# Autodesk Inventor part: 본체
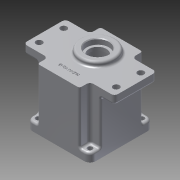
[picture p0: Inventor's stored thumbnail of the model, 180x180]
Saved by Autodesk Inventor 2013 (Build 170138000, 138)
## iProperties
Created: 2015-07
Part Number: 본체
Material: 알루미늄 6061
Document SubType Name: 판금
Designer: user
Density: 1 g/cm^3
Sheet Metal Rule: 기본값
Author: user
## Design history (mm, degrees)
node "작업 평면1"
sketch "스케치2"
  geometry: L1 (-30, 45)-(30, 45); L2 (30, -45)-(-30, -45); L3 (65, 30)-(65, -30); L4 (-65, -30)-(-65, 30); L5 (-30, -45)-(-30, -35); L6 (-30, 35)-(-30, 45); L7 (-65, 30)-(-35, 30); L8 (35, 30)-(65, 30); L9 (30, 45)-(30, 35); L10 (30, -35)-(30, -45); L11 (65, -30)-(35, -30); L12 (-35, -30)-(-65, -30); A1 r 5 centre (-35, 35) between (-35, 30) and (-30, 35); A2 r 5 centre (35, 35) between (30, 35) and (35, 30); A3 r 5 centre (35, -35) between (35, -30) and (30, -35); A4 r 5 centre (-35, -35) between (-30, -35) and (-35, -30); 4 further points
  constraints: 24 end point, 10 parallel, 8 point on circle, 8 tangent, 4 centre point, 4 perpendicular, 3 equal radius, 3 horizontal, 2 horizontal alignment, 2 midpoint, 1 vertical alignment
  dimensions: "d5" = 60 distance of L2.start L2.end; "d6" = 90 distance of L1.end L2.start; "d9" = 130 distance of L3.end L4.start; "d10" = 60 distance of L3.start L3.end; "d11" = 65 distance from line of L4 point (0, 0); "d12" = 5 radius of A1
extrude "돌출2" join sketch "스케치2" distance "d13" = 12; taper "d14" = 0 deg
sketch "스케치4"
  geometry: L1 (-30, 45)-(30, 45); L2 (30, 45)-(30, -45); L3 (30, -45)-(-30, -45); L4 (-30, -45)-(-30, 45); 1 further point
  constraints: 8 end point, 2 parallel, 1 horizontal, 1 perpendicular
extrude "돌출3" join sketch "스케치4" distance "d19" = 63; taper "d20" = 0 deg
sketch "스케치5"
  geometry: L1 (35, 30)-(65, 30) reference; L2 (65, 30)-(65, -30) reference; L3 (65, -30)-(35, -30) reference; L4 (30, 35)-(30, -35) reference; L5 (30, 45)-(30, 35) reference; L6 (-30, 45)-(30, 45) reference; L7 (-30, 35)-(-30, 45) reference; L8 (-65, 30)-(-35, 30) reference; L9 (-65, -30)-(-65, 30) reference; L10 (-35, -30)-(-65, -30) reference; L11 (-30, -35)-(-30, 35) reference; L12 (30, -35)-(30, -45) reference; L13 (30, -45)-(-30, -45) reference; L14 (-30, -45)-(-30, -35) reference; L15 (30, 30)-(46, 30); L16 (46, 30)-(46, -30); L17 (46, -30)-(30, -30); L18 (30, -30)-(30, 30); L19 (-46, 30)-(-46, -30); L20 (-30, -30)-(-30, 30); L21 (-30, 30)-(-46, 30); L22 (-46, -30)-(-30, -30); A1 r 5 centre (35, 35) between (30, 35) and (35, 30) reference; A2 r 5 centre (35, -35) between (35, -30) and (30, -35) reference; A3 r 5 centre (-35, 35) between (-35, 30) and (-30, 35) reference; A4 r 5 centre (-35, -35) between (-30, -35) and (-35, -30) reference; 1 further point
  constraints: 16 end point, 3 parallel, 1 horizontal, 1 perpendicular, 1 point on line
  dimensions: "d21" = 16 distance of L16.end L17.end; "d22" = 60 distance of L15.end L16.end; "d23" = 90 deg angle of L2 L21; "d24" = 90 deg angle of L2 L22; "d25" = 90 deg angle of L3 L20; "d26" = 111 distance between parallel lines of L2 L19; "d27" = 60 distance between parallel lines of L3 L15; "d28" = 95 distance from line of L1.end L20; "d29" = 0 distance from line of L1.end L21; "d30" = 60 distance from line of L1.end L22
extrude "돌출4" join sketch "스케치5" distance "d31" = 63; taper "d32" = 0 deg
fillet "모깎기1" dims "d33" = 5
sketch "스케치6"
  geometry: L1 (-45, 45)-(45, 45); L2 (45, 45)-(45, -45); L3 (45, -45)-(-45, -45); L4 (-45, -45)-(-45, 45); 3 further points
  constraints: 8 end point, 2 midpoint, 2 parallel, 1 horizontal, 1 horizontal alignment, 1 perpendicular, 1 vertical alignment
  dimensions: "d34" = 90 distance of L2.end L3.end; "d35" = 90 distance of L1.end L2.end
extrude "돌출5" join sketch "스케치6" distance "d36" = 12; taper "d37" = 0 deg
sketch "스케치7"
  geometry: L1 (45, 45)-(-45, 45) reference; L2 (-45, 45)-(-45, -45) reference; L3 (-45, -45)-(45, -45) reference; L4 (45, -45)-(45, 45) reference; 1 further point
sketch "스케치8"
  geometry: L1 (45, 45)-(-45, 45) reference; L2 (-45, 45)-(-45, -45) reference; L3 (-45, -45)-(45, -45) reference; L4 (45, -45)-(45, 45) reference; 1 further point
sketch "스케치9"
  geometry: L1 (45, 45)-(-45, 45) reference; L2 (-45, 45)-(-45, -45) reference; L3 (-45, -45)-(45, -45) reference; L4 (45, -45)-(45, 45) reference; 1 further point
sketch "스케치10"
  geometry: L1 (-37, 37)-(37, 37); L2 (37, 37)-(37, -37); L3 (37, -37)-(-37, -37); L4 (-37, -37)-(-37, 37); C1 r 3.5 at (-37, 37); C2 r 3.5 at (37, 37); C3 r 3.5 at (-37, -37); C4 r 3.5 at (37, -37); 3 further points
  constraints: 8 end point, 4 centre point, 4 coincident, 2 midpoint, 2 parallel, 1 horizontal, 1 horizontal alignment, 1 perpendicular, 1 vertical alignment
  dimensions: "d38" = 74 distance of L2.end L3.end; "d39" = 74 distance of L1.end L2.end; "d40" = 7 diameter of C1; "d41" = 7 diameter of C2; "d42" = 7 diameter of C3; "d43" = 7 diameter of C4
extrude "돌출6" cut sketch "스케치10" distance "d44" = 12; taper "d45" = 0 deg
fillet "모깎기2" dims "d46" = 8
sketch "스케치11"
  geometry: L1 (-55, 17.5)-(55, 17.5); L2 (55, 17.5)-(55, -17.5); L3 (55, -17.5)-(-55, -17.5); L4 (-55, -17.5)-(-55, 17.5); 7 further points
  constraints: 8 end point, 4 coincident, 2 midpoint, 2 parallel, 1 horizontal, 1 horizontal alignment, 1 perpendicular, 1 vertical alignment
  dimensions: "d47" = 110 distance of L2.end L3.end; "d48" = 35 distance of L1.end L2.end
hole "구멍1" sketch "스케치11" at (-55, 17.5), (55, 17.5), (55, -17.5), (-55, -17.5) diameter "d49" = 9; stored, may be unused: countersink angle "d53" = 90 deg, drill point angle "d55" = 118 deg; dims "d50" = 6, "d51" = 4, "d52" = 2, "d54" = 0.5 (derived)
fillet "모깎기3" dims "d56" = 5
sketch "스케치12"
  geometry: L1 (67, 75)-(67, 87) reference; L2 (-7, 87)-(67, 87) reference; L3 (-7, 75)-(-7, 87) reference; L4 (0, 75)-(-7, 75) reference; L5 (0, 0)-(0, 75) reference; L6 (60, 0)-(0, 0) reference; L7 (60, 75)-(60, 0) reference; L8 (67, 75)-(60, 75) reference; L9 (-16, 12)-(-16, 75) reference; L10 (-15, 87)-(-15, 75) reference; L11 (76, 12)-(76, 75) reference; L12 (75, 75)-(67, 75) reference; L13 (75, 75)-(75, 87) reference; L14 (75, 75)-(76, 75); L15 (76, 75)-(76, 12); L16 (76, 12)-(75, 12); L17 (75, 12)-(75, 75); L18 (-15, 75)-(-16, 75); L19 (-16, 75)-(-16, 12); L20 (-16, 12)-(-15, 12); L21 (-15, 12)-(-15, 75); 1 further point
  constraints: 16 end point, 4 parallel, 2 horizontal, 2 perpendicular
extrude "돌출7" cut sketch "스케치12" distance "d57" = 63; taper "d58" = 0 deg
sketch "스케치13"
  geometry: 1 further point
hole "구멍2" sketch "스케치13" at (0, 0) diameter "d59" = 80; stored, may be unused: countersink angle "d63" = 90 deg, drill point angle "d65" = 0 deg; dims "d60" = 6, "d61" = 4, "d62" = 2, "d64" = 9
sketch "스케치15"
  geometry: C1 r 40 at (0, 0) reference; C2 r 39 at (0, 0)
  constraints: 1 centre point, 1 coincident
  dimensions: "d77" = 78 diameter of C2
extrude "돌출8" cut sketch "스케치15" distance "d78" = 52; taper "d79" = 0 deg
node "작업 평면2"
sketch "스케치16" dims "d81" = 70
  geometry: L1 (0, 0)-(60.287, 60.287); L2 (0, 0)-(85.258, 0); A1 r 4 centre (24.749, 24.749) between (23.219, 28.445) and (28.445, 23.219); A2 r 40 centre (0, 0) between (25.309, 30.975) and (30.975, 25.309) reference; A3 r 3.5 centre (31.678, 21.88) between (30.975, 25.309) and (28.445, 23.219); A4 r 3.5 centre (21.88, 31.678) between (23.219, 28.445) and (25.309, 30.975); A5 r 3.5 centre (-31.678, 21.88) between (-28.445, 23.219) and (-30.975, 25.309); A6 r 4 centre (-24.749, 24.749) between (-28.445, 23.219) and (-23.219, 28.445); A7 r 3.5 centre (-21.88, 31.678) between (-25.309, 30.975) and (-23.219, 28.445); A8 r 3.5 centre (-21.88, -31.678) between (-23.219, -28.445) and (-25.309, -30.975); A9 r 4 centre (-24.749, -24.749) between (-23.219, -28.445) and (-28.445, -23.219); A10 r 3.5 centre (-31.678, -21.88) between (-30.975, -25.309) and (-28.445, -23.219); A11 r 3.5 centre (31.678, -21.88) between (28.445, -23.219) and (30.975, -25.309); A12 r 4 centre (24.749, -24.749) between (28.445, -23.219) and (23.219, -28.445); A13 r 3.5 centre (21.88, -31.678) between (25.309, -30.975) and (23.219, -28.445); 1 further point
  constraints: 26 point on circle, 12 centre point, 4 end point, 1 coincident, 1 equal length, 1 horizontal, 1 point on line, 1 symmetric about line, 1 tangent, 46 other
  dimensions: "d82" = 45 deg angle of L2 L1; "d83" = 8 diameter of A1; "d84" = 7 diameter of A3; "d87" = 360 deg dimension on point (0, 0) A4.centre (derived)
extrude "돌출9" join sketch "스케치16" distance "d89" = 54; taper "d90" = 0 deg
fillet "모깎기4" dims "d94" = 3.5
sketch "스케치17"
  geometry: L1 (-65, -25)-(-65, 25) reference; L2 (0, 0)-(0, 11); C1 r 25 at (0, 11)
  constraints: 2 end point, 1 centre point, 1 coincident, 1 parallel
  dimensions: "d95" = 11 distance of L2.start L2.end; "d96" = 50 diameter of C1
extrude "돌출10" join sketch "스케치17" distance "d97" = 7; taper "d98" = 0 deg
sketch "스케치18"
  geometry: C1 r 25 at (0, 0) reference; 1 further point
hole "구멍3" sketch "스케치18" at (0, 0) diameter "d99" = 25; stored, may be unused: countersink angle "d103" = 90 deg, drill point angle "d105" = 0 deg; dims "d100" = 6, "d101" = 32, "d102" = 8, "d104" = 13
sketch "스케치19"
  geometry: C1 r 12.5 at (0, 0) reference; 1 further point
hole "구멍4" sketch "스케치19" at (0, 0) diameter "d106" = 35; stored, may be unused: countersink angle "d110" = 90 deg, drill point angle "d112" = 0 deg; dims "d107" = 6, "d108" = 32, "d109" = 8, "d111" = 10
sketch "스케치20"
  geometry: A1 r 20.5 centre (0, 11) between (7.402, -8.117) and (-7.402, -8.117); A2 r 14 centre (0, -20) between (-7.402, -8.117) and (7.402, -8.117); 4 further points
  constraints: 4 point on circle, 2 centre point
  dimensions: "d114" = 41 diameter of A1; "d116" = 28 diameter of A2; "d117" = 29.51258 distance of point (27.462, 21.809) A1.centre; "d118" = 42.7856 distance of point (27.462, -21.809) A1.centre; "d119" = 28.22581 distance of point (21.134, -32.777) A1.start; "d120" = 23.05058 distance of point (-21.809, -27.462) A2.centre
extrude "돌출11" cut sketch "스케치20" distance "d121" = 7; taper "d122" = 0 deg
sketch "스케치21"
  geometry: L1 (-46, -30)-(-46, -18) reference; L2 (-45, -18)-(-45, -30); L3 (-46, -18)-(-45, -18); L4 (-45, -18)-(-45, -30); L5 (-45, -30)-(-46, -30); L6 (-46, -30)-(-46, -18); 1 further point
  constraints: 10 end point, 3 parallel, 1 horizontal, 1 perpendicular
extrude "돌출12" cut sketch "스케치21" distance "d123" = 63; taper "d124" = 0 deg
sketch "스케치22"
  geometry: L1 (45, -18)-(46, -18); L2 (46, -18)-(46, -30); L3 (46, -30)-(45, -30); L4 (45, -30)-(45, -18); 1 further point
  constraints: 8 end point, 2 parallel, 1 horizontal, 1 perpendicular
extrude "돌출13" cut sketch "스케치22" distance "d125" = 63; taper "d126" = 0 deg
sketch "스케치23"
  geometry: A1 r 14 centre (0, -20) between (-7.402, -8.117) and (7.402, -8.117) reference; 1 further point
hole "구멍5" sketch "스케치23" at (0, -20) diameter "d127" = 19; stored, may be unused: countersink angle "d131" = 90 deg, drill point angle "d133" = 0 deg; dims "d128" = 6, "d129" = 22, "d130" = 7, "d132" = 8
node "스케치24"
sketch "스케치25" dims "d134" = 70
  geometry: L1 (0, 0)-(46.617, 46.617); L2 (0, 0)-(65.927, 0); C1 r 40 at (0, 0) reference; 1 further point
  constraints: 4 end point, 1 coincident, 1 equal length, 1 horizontal, 1 point on line, 3 other
  dimensions: "d135" = 45 deg angle of L2 L1
hole "구멍6" sketch "스케치25" at (24.749, 24.749) diameter "d136" = 3.242; stored, may be unused: countersink angle "d140" = 90 deg, drill point angle "d142" = 118 deg; dims "d137" = 12, "d138" = 22, "d139" = 7, "d141" = 15
sketch "스케치26"
  geometry: C1 r 17.5 at (0, 0) reference; C2 r 17.5 at (0, 0); 1 further point
  constraints: 1 centre point, 1 coincident, 1 concentric
extrude "돌출14" cut sketch "스케치26" distance "d146" = 63; taper "d147" = 0 deg
fillet "모깎기5" dims "d148" = 3
fillet "모깎기6" dims "d149" = 3
fillet "모깎기7" dims "d150" = 3
fillet "모깎기8" dims "d151" = 3
sketch "스케치27"
  geometry: L1 (27, -45)-(-27, -45) reference; L2 (0, -45)-(0, -30); 2 further points
  constraints: 2 end point, 1 coincident, 1 midpoint, 1 perpendicular, 1 other
  dimensions: "d152" = 15 distance of L2.start L2.end
feature "엠보싱1" sketch "스케치27" dims "d14" = 0, "d153" = 0.5, "d154" = 0
fillet "모깎기9" dims "d155" = 0.3
fillet "모깎기10" dims "d156" = 3
chamfer "모따기1" distance "d157" = 1; stored, may be unused: second distance "d158" = 2, angle "d159" = 45 deg
node "솔리드1"
pattern_circular "원형 패턴1" dims angle "d92" = 360 deg
pattern_circular "원형 패턴2" dims angle "d144" = 360 deg
node "절단 모서리 투영1"
node "절단 모서리 투영2"
other parameters: "K계수" = 4.4, "BendRadius" = 0.5 (derived), "BendReliefWidth" = 0.5 (derived), "BendReliefDepth" = 0.25 (derived), "CornerReliefSize" = 2 (derived), "SeamGap" = 0.01, "MinimumRemnant" = 1 (derived), "TransitionRadius" = 0.5 (= BendRadius), "d80" = -9
